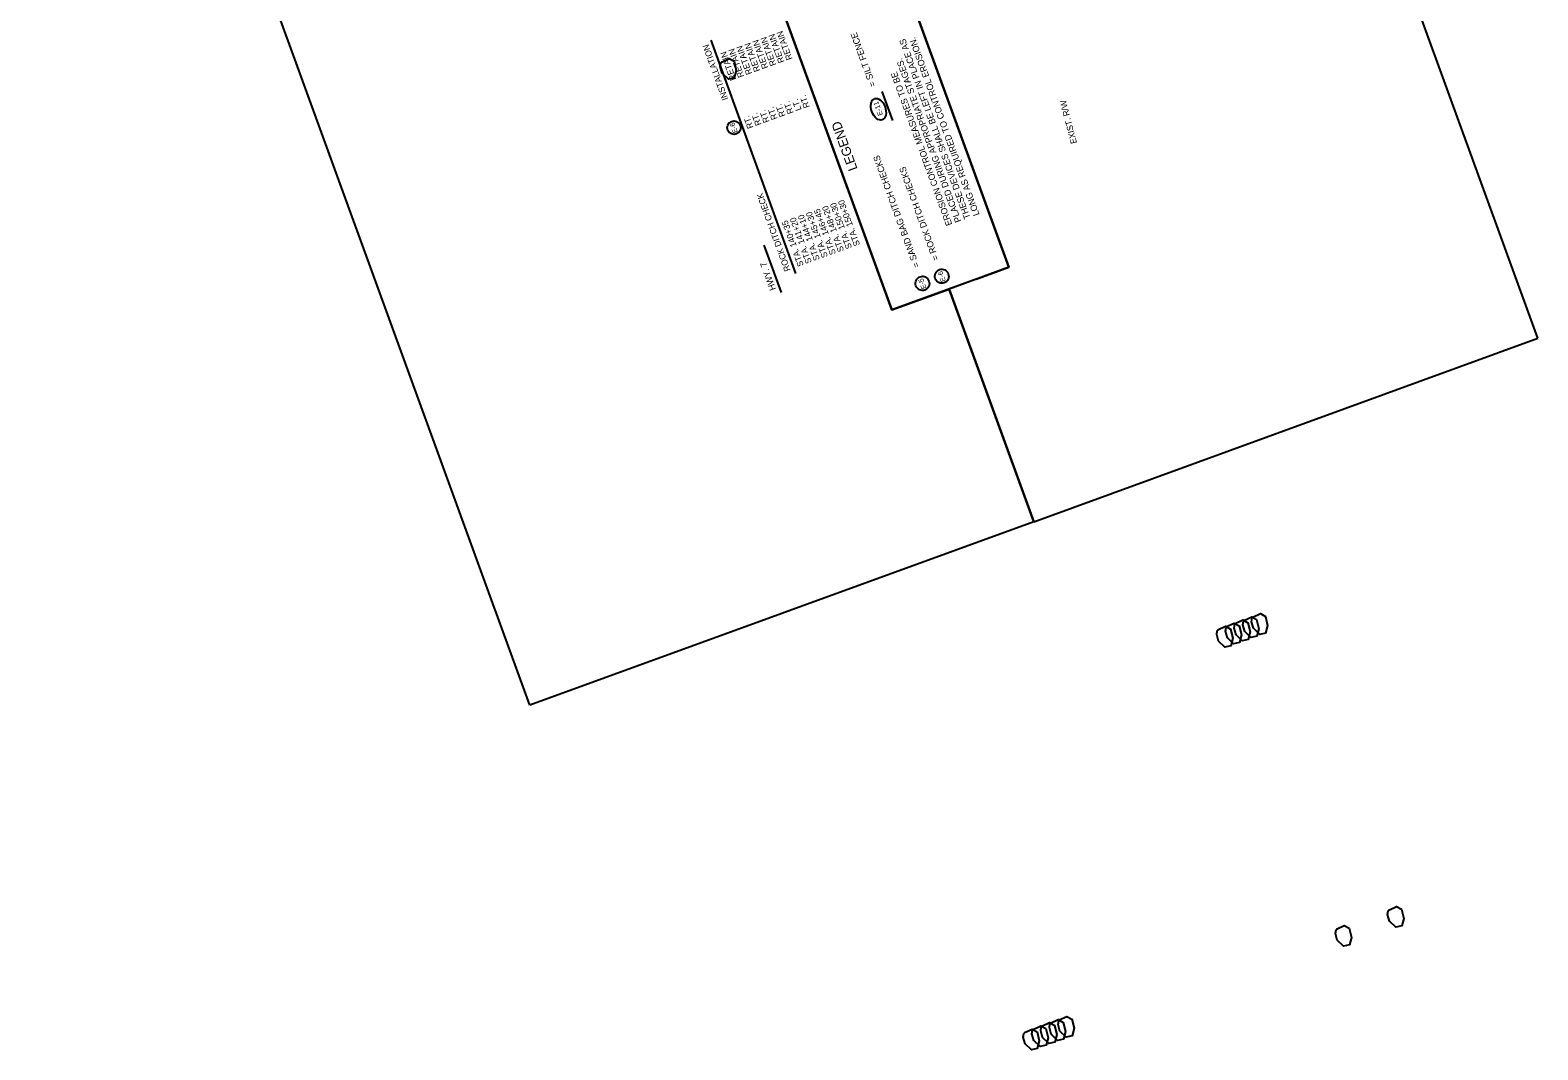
# Model space of a CAD drawing. Extents: x 986289 to 987754, y 1870781 to 1872971.
# Drawn here: x 986289 to 987754, y 1870781 to 1871771 of the extents above; entities that cross this region are included whole.
import ezdxf

# ---------------------------------------------------------------- set-up
doc = ezdxf.new("R2010")
doc.units = 0
for name, color, linetype in [('1', 7, 'Continuous'), ('44', 7, 'Continuous'), ('Level 1', 7, 'Continuous'), ('Level 44', 7, 'Continuous'), ('NO PLOT', 7, 'Continuous'), ('R_Draft', 7, 'Continuous'), ('S_TREE', 7, 'Continuous')]:
    doc.layers.add(name, color=color, linetype=linetype)

msp = doc.modelspace()

# ---------------------------------------------------------------- linework, layer by layer
at = {"layer": '1'}
for p, q in [((987125.9, 1871499.6), (987008.8, 1871821.6)), ((987207.8, 1871529.4), (987125.9, 1871499.6)), ((987263.9, 1871293.8), (987181.7, 1871519.9))]:
    msp.add_line(p, q, dxfattribs=at)
msp.add_lwpolyline([(987207.8, 1871529.4), (987239.7, 1871541), (987122.5, 1871863)], dxfattribs=at)
msp.add_circle((986972.6, 1871676.6), 6.61, dxfattribs=at)
at = {"layer": '44'}
for p, q in [((987032.8, 1871535.1), (986950.4, 1871761.6)), ((987018.7, 1871516.5), (987002, 1871562.4))]:
    msp.add_line(p, q, dxfattribs=at)
at = {"layer": 'Level 1'}
for centre, major_axis, ratio in [((987112.9, 1871694.5), (-3.7, 10.3), 0.622952), ((987174.5, 1871532.3), (2.35, -6.47), 0.97521), ((987155.7, 1871525.4), (2.35, -6.47), 0.97521)]:
    msp.add_ellipse(centre, major_axis=major_axis, ratio=ratio, dxfattribs=at)
at = {"layer": 'Level 44'}
msp.add_lwpolyline([(987126.8, 1871683.5), (987116.5, 1871711.8)], dxfattribs=at)
at = {"layer": 'NO PLOT'}
for points in [[(987753.7, 1871472.1), (987208, 1872971.2), (986718.3, 1872793), (986821.2, 1872510.2), (986884.7, 1872533.2), (987030, 1872133.9), (986966.6, 1872110.8), (987064.5, 1871841.9), (987122.5, 1871863), (987239.7, 1871541), (987181.7, 1871519.9), (987263.9, 1871293.8)], [(987753.7, 1871472.1), (987208, 1872971.2), (986718.3, 1872793), (986821.2, 1872510.2), (986884.7, 1872533.2), (987030, 1872133.9), (986966.6, 1872110.8), (987064.5, 1871841.9), (987122.5, 1871863), (987239.7, 1871541), (987181.7, 1871519.9), (987263.9, 1871293.8)], [(987753.7, 1871472.1), (987208, 1872971.2), (986718.3, 1872793), (986821.2, 1872510.2), (986884.7, 1872533.2), (987030, 1872133.9), (986966.6, 1872110.8), (987064.5, 1871841.9), (987122.5, 1871863), (987239.7, 1871541), (987181.7, 1871519.9), (987263.9, 1871293.8)], [(987753.7, 1871472.1), (987208, 1872971.2), (986718.3, 1872793), (986821.2, 1872510.2), (986884.7, 1872533.2), (987030, 1872133.9), (986966.6, 1872110.8), (987064.5, 1871841.9), (987122.5, 1871863), (987239.7, 1871541), (987181.7, 1871519.9), (987263.9, 1871293.8)], [(987753.7, 1871472.1), (987208, 1872971.2), (986718.3, 1872793), (986821.2, 1872510.2), (986884.7, 1872533.2), (987030, 1872133.9), (986966.6, 1872110.8), (987064.5, 1871841.9), (987122.5, 1871863), (987239.7, 1871541), (987181.7, 1871519.9), (987263.9, 1871293.8)], [(986774.2, 1871115.6), (986369.2, 1872228.3), (986415.6, 1872245.1), (986348.7, 1872429.1), (986362.4, 1872434.1), (986288.7, 1872636.6), (986718.3, 1872793), (986821.2, 1872510.2), (986748.9, 1872483.8), (986894.2, 1872084.4), (986966.6, 1872110.8), (987064.5, 1871841.9), (987008.8, 1871821.6), (987125.9, 1871499.6), (987181.7, 1871519.9), (987263.9, 1871293.8)], [(986774.2, 1871115.6), (986369.2, 1872228.3), (986415.6, 1872245.1), (986348.7, 1872429.1), (986362.4, 1872434.1), (986288.7, 1872636.6), (986718.3, 1872793), (986821.2, 1872510.2), (986748.9, 1872483.8), (986894.2, 1872084.4), (986966.6, 1872110.8), (987064.5, 1871841.9), (987008.8, 1871821.6), (987125.9, 1871499.6), (987181.7, 1871519.9), (987263.9, 1871293.8)], [(986774.2, 1871115.6), (986369.2, 1872228.3), (986415.6, 1872245.1), (986348.7, 1872429.1), (986362.4, 1872434.1), (986288.7, 1872636.6), (986718.3, 1872793), (986821.2, 1872510.2), (986748.9, 1872483.8), (986894.2, 1872084.4), (986966.6, 1872110.8), (987064.5, 1871841.9), (987008.8, 1871821.6), (987125.9, 1871499.6), (987181.7, 1871519.9), (987263.9, 1871293.8)], [(986774.2, 1871115.6), (986369.2, 1872228.3), (986415.6, 1872245.1), (986348.7, 1872429.1), (986362.4, 1872434.1), (986288.7, 1872636.6), (986718.3, 1872793), (986821.2, 1872510.2), (986748.9, 1872483.8), (986894.2, 1872084.4), (986966.6, 1872110.8), (987064.5, 1871841.9), (987008.8, 1871821.6), (987125.9, 1871499.6), (987181.7, 1871519.9), (987263.9, 1871293.8)], [(986774.2, 1871115.6), (986369.2, 1872228.3), (986415.6, 1872245.1), (986348.7, 1872429.1), (986362.4, 1872434.1), (986288.7, 1872636.6), (986718.3, 1872793), (986821.2, 1872510.2), (986748.9, 1872483.8), (986894.2, 1872084.4), (986966.6, 1872110.8), (987064.5, 1871841.9), (987008.8, 1871821.6), (987125.9, 1871499.6), (987181.7, 1871519.9), (987263.9, 1871293.8)]]:
    msp.add_lwpolyline(points, close=True, dxfattribs=at)
at = {"layer": 'S_TREE'}
for points in [[(986960.3, 1871740.3), (986967.8, 1871743.8), (986972.6, 1871741.1), (986974.8, 1871732.3), (986972.8, 1871724.9), (986967.1, 1871723.6), (986961.1, 1871729.5), (986959.2, 1871735.9), (986959.8, 1871739.6), (986961, 1871740.8)], [(987468.1, 1871198.1), (987475.6, 1871201.6), (987480.4, 1871198.9), (987482.6, 1871190), (987480.6, 1871182.7), (987474.9, 1871181.4), (987468.9, 1871187.3), (987467, 1871193.7), (987467.6, 1871197.4), (987468.8, 1871198.6)], [(987468.1, 1871198.1), (987475.6, 1871201.6), (987480.4, 1871198.9), (987482.6, 1871190), (987480.6, 1871182.7), (987474.9, 1871181.4), (987468.9, 1871187.3), (987467, 1871193.7), (987467.6, 1871197.4), (987468.8, 1871198.6)], [(987468.1, 1871198.1), (987475.6, 1871201.6), (987480.4, 1871198.9), (987482.6, 1871190), (987480.6, 1871182.7), (987474.9, 1871181.4), (987468.9, 1871187.3), (987467, 1871193.7), (987467.6, 1871197.4), (987468.8, 1871198.6)], [(987468.1, 1871198.1), (987475.6, 1871201.6), (987480.4, 1871198.9), (987482.6, 1871190), (987480.6, 1871182.7), (987474.9, 1871181.4), (987468.9, 1871187.3), (987467, 1871193.7), (987467.6, 1871197.4), (987468.8, 1871198.6)], [(987476.6, 1871201.2), (987484.1, 1871204.7), (987488.9, 1871202), (987491, 1871193.1), (987489.1, 1871185.7), (987483.4, 1871184.5), (987477.3, 1871190.4), (987475.5, 1871196.8), (987476.1, 1871200.5), (987477.3, 1871201.7)], [(987476.6, 1871201.2), (987484.1, 1871204.7), (987488.9, 1871202), (987491, 1871193.1), (987489.1, 1871185.7), (987483.4, 1871184.5), (987477.3, 1871190.4), (987475.5, 1871196.8), (987476.1, 1871200.5), (987477.3, 1871201.7)], [(987442.8, 1871188.9), (987450.2, 1871192.4), (987455.1, 1871189.6), (987457.2, 1871180.8), (987455.3, 1871173.4), (987449.6, 1871172.2), (987443.5, 1871178), (987441.6, 1871184.5), (987442.2, 1871188.1), (987443.4, 1871189.4)], [(987451.2, 1871192), (987458.7, 1871195.5), (987463.5, 1871192.7), (987465.7, 1871183.9), (987463.7, 1871176.5), (987458, 1871175.2), (987452, 1871181.1), (987450.1, 1871187.6), (987450.7, 1871191.2), (987451.9, 1871192.4)], [(987451.2, 1871192), (987458.7, 1871195.5), (987463.5, 1871192.7), (987465.7, 1871183.9), (987463.7, 1871176.5), (987458, 1871175.2), (987452, 1871181.1), (987450.1, 1871187.6), (987450.7, 1871191.2), (987451.9, 1871192.4)], [(987459.7, 1871195), (987467.1, 1871198.5), (987472, 1871195.8), (987474.1, 1871187), (987472.2, 1871179.6), (987466.5, 1871178.3), (987460.4, 1871184.2), (987458.6, 1871190.6), (987459.2, 1871194.3), (987460.4, 1871195.5)], [(987459.7, 1871195), (987467.1, 1871198.5), (987472, 1871195.8), (987474.1, 1871187), (987472.2, 1871179.6), (987466.5, 1871178.3), (987460.4, 1871184.2), (987458.6, 1871190.6), (987459.2, 1871194.3), (987460.4, 1871195.5)], [(987608.8, 1870916.8), (987616.3, 1870920.3), (987621.1, 1870917.5), (987623.3, 1870908.7), (987621.4, 1870901.3), (987615.7, 1870900.1), (987609.6, 1870905.9), (987607.7, 1870912.4), (987608.3, 1870916), (987609.5, 1870917.3)], [(987558.1, 1870898.3), (987565.6, 1870901.8), (987570.4, 1870899.1), (987572.5, 1870890.2), (987570.6, 1870882.9), (987564.9, 1870881.6), (987558.8, 1870887.5), (987557, 1870893.9), (987557.6, 1870897.6), (987558.8, 1870898.8)], [(987558.1, 1870898.3), (987565.6, 1870901.8), (987570.4, 1870899.1), (987572.5, 1870890.2), (987570.6, 1870882.9), (987564.9, 1870881.6), (987558.8, 1870887.5), (987557, 1870893.9), (987557.6, 1870897.6), (987558.8, 1870898.8)], [(987271.7, 1870803.9), (987279.2, 1870807.4), (987284, 1870804.6), (987286.2, 1870795.8), (987284.2, 1870788.4), (987278.5, 1870787.2), (987272.4, 1870793), (987270.6, 1870799.5), (987271.2, 1870803.1), (987272.4, 1870804.4)], [(987271.7, 1870803.9), (987279.2, 1870807.4), (987284, 1870804.6), (987286.2, 1870795.8), (987284.2, 1870788.4), (987278.5, 1870787.2), (987272.4, 1870793), (987270.6, 1870799.5), (987271.2, 1870803.1), (987272.4, 1870804.4)], [(987280.2, 1870807), (987287.6, 1870810.5), (987292.5, 1870807.7), (987294.6, 1870798.9), (987292.7, 1870791.5), (987287, 1870790.2), (987280.9, 1870796.1), (987279, 1870802.6), (987279.6, 1870806.2), (987280.8, 1870807.4)], [(987288.6, 1870810), (987296.1, 1870813.5), (987300.9, 1870810.8), (987303.1, 1870802), (987301.1, 1870794.6), (987295.4, 1870793.3), (987289.3, 1870799.2), (987287.5, 1870805.6), (987288.1, 1870809.3), (987289.3, 1870810.5)], [(987254.8, 1870797.7), (987262.3, 1870801.2), (987267.1, 1870798.5), (987269.2, 1870789.7), (987267.3, 1870782.3), (987261.6, 1870781), (987255.5, 1870786.9), (987253.7, 1870793.3), (987254.3, 1870797), (987255.5, 1870798.2)], [(987254.8, 1870797.7), (987262.3, 1870801.2), (987267.1, 1870798.5), (987269.2, 1870789.7), (987267.3, 1870782.3), (987261.6, 1870781), (987255.5, 1870786.9), (987253.7, 1870793.3), (987254.3, 1870797), (987255.5, 1870798.2)], [(987263.2, 1870800.8), (987270.7, 1870804.3), (987275.5, 1870801.6), (987277.7, 1870792.7), (987275.8, 1870785.4), (987270.1, 1870784.1), (987264, 1870790), (987262.1, 1870796.4), (987262.7, 1870800.1), (987263.9, 1870801.3)], [(987263.2, 1870800.8), (987270.7, 1870804.3), (987275.5, 1870801.6), (987277.7, 1870792.7), (987275.8, 1870785.4), (987270.1, 1870784.1), (987264, 1870790), (987262.1, 1870796.4), (987262.7, 1870800.1), (987263.9, 1870801.3)]]:
    msp.add_lwpolyline(points, dxfattribs=at)

# ---------------------------------------------------------------- texts
at = {"layer": '1'}
msp.add_text('E-6 ', height=4.8, rotation=110, dxfattribs=at).set_placement((986976.3, 1871672.4))
at = {"layer": '44'}
for s, height, p in [('INSTALLATION', 6, (986967.1, 1871704.5)), ('RETAIN', 6, (986998.2, 1871732.1)), ('RETAIN', 6, (987006, 1871735)), ('RETAIN', 6, (987013.8, 1871737.8)), ('RETAIN', 6, (987021.7, 1871740.7)), ('RETAIN', 6, (987029.5, 1871743.5)), ('RETAIN', 6, (986974.8, 1871723.6)), ('RETAIN', 6, (986982.6, 1871726.5)), ('RETAIN', 6, (986990.4, 1871729.3)), ('RT.', 6, (987022.8, 1871688.3)), ('RT.', 6, (987030.7, 1871691.2)), ('LT.', 6, (987038.4, 1871694.2)), ('RT.', 6, (987046.3, 1871696.9)), ('RT.', 6, (986991.6, 1871676.9)), ('RT.', 6, (986999.4, 1871679.8)), ('RT.', 6, (987007.2, 1871682.6)), ('RT.', 6, (987015, 1871685.5)), ('ROCK DITCH CHECK', 6, (987027.6, 1871538.3)), ('STA. 146+45', 6, (987071.7, 1871554.4)), ('STA. 148+20', 6, (987079.6, 1871557.2)), ('STA. 150+30', 6, (987087.4, 1871560.1)), ('STA. 150+30', 6, (987095.2, 1871562.9)), ('STA. 140+35', 6, (987040.5, 1871543)), ('STA. 141+20', 6, (987048.3, 1871545.9)), ('STA. 144+10', 6, (987056.1, 1871548.7)), ('STA. 145+30', 6, (987063.9, 1871551.5)), ('HWY. 7', 6.25, (987013.5, 1871519.8))]:
    msp.add_text(s, height=height, rotation=110, dxfattribs=at).set_placement(p)
at = {"layer": 'Level 1'}
for s, height, p in [('= SILT FENCE', 6.25, (987110.6, 1871717.6)), ('THESE DEVICES SHALL BE LEFT IN PLACE AS ', 6.25, (987202.4, 1871589.1)), ('LONG AS REQUIRED TO CONTROL EROSION.', 6.25, (987211.3, 1871592.3)), ('PLACED DURING APPROPRIATE STAGES. ', 6.25, (987193.6, 1871585.9)), ('EROSION CONTROL MEASURES TO BE', 6.25, (987184.8, 1871582.7)), ('E-11 ', 4.88, (987117.3, 1871689.3)), ('= SAND BAG DITCH CHECKS', 6.25, (987153, 1871542)), ('= ROCK DITCH CHECKS', 6.25, (987171.8, 1871548.9)), ('E-5 ', 4.88, (987159.7, 1871520.9)), ('E-6 ', 4.88, (987178.4, 1871527.9))]:
    msp.add_text(s, height=height, rotation=110, dxfattribs=at).set_placement(p)
at = {"layer": 'Level 44'}
msp.add_text('LEGEND', height=9.14, rotation=110, dxfattribs=at).set_placement((987092.8, 1871636.6))
at = {"layer": 'R_Draft'}
msp.add_text('EXIST. R/W', height=6, rotation=104.7013, dxfattribs=at).set_placement((987305.9, 1871661.9))

doc.saveas('drawing.dxf')
